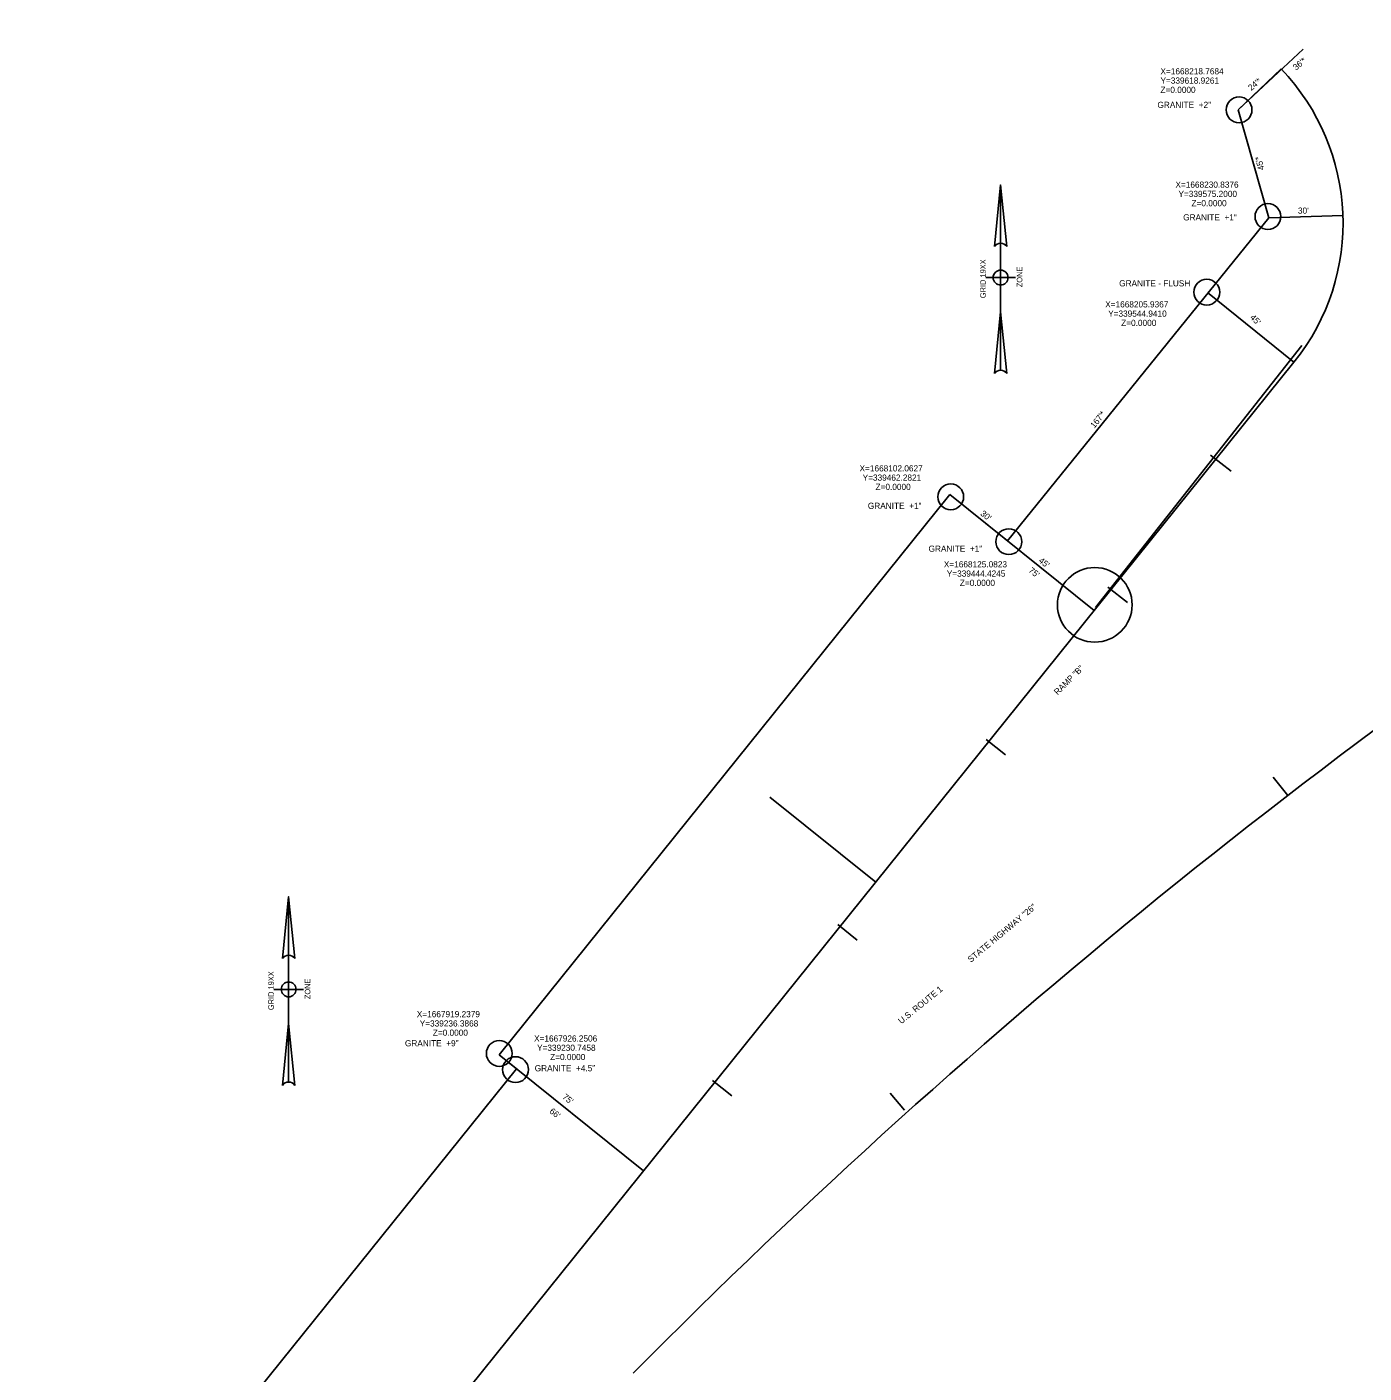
# Model space of a CAD drawing. Extents: x 1663896 to 1668965, y 337017 to 340013.
# Drawn here: x 1667728 to 1668269, y 339108 to 339653 of the extents above; entities that cross this region are included whole.
import ezdxf

# ---------------------------------------------------------------- set-up
doc = ezdxf.new("R2010")
doc.units = 0
for name, color, linetype in [('E_ROW_Line', 7, 'Continuous'), ('E_ROW_TieLine', 7, 'Continuous'), ('MISCELLN TEXT', 7, 'Continuous'), ('North Arrows', 7, 'Continuous')]:
    doc.layers.add(name, color=color, linetype=linetype)

msp = doc.modelspace()

# ---------------------------------------------------------------- linework, layer by layer
at = {"layer": 'E_ROW_Line'}
for p, q in [((1668218.45, 339618.89), (1668230.84, 339575.2)), ((1668230.84, 339575.2), (1668125.08, 339444.42)), ((1667919.24, 339236.39), (1668101.71, 339463.23)), ((1668125.08, 339444.42), (1668101.71, 339463.23)), ((1667926.25, 339230.75), (1667919.24, 339236.39)), ((1667728.11, 338984.42), (1667926.25, 339230.75))]:
    msp.add_line(p, q, dxfattribs=at)
at = {"layer": 'E_ROW_TieLine'}
for p, q in [((1668218.45, 339618.89), (1668244.77, 339643.45)), ((1668235.75, 339635.52), (1668218.45, 339618.89)), ((1668218.45, 339618.89), (1668230.84, 339575.2)), ((1668260.82, 339576.23), (1668230.84, 339575.2)), ((1668230.84, 339575.2), (1668125.08, 339444.42)), ((1668241, 339516.74), (1668205.94, 339544.94)), ((1668160.69, 339417.44), (1668244.23, 339523.48)), ((1667779.54, 338943.05), (1668241, 339516.74)), ((1668207.16, 339479.09), (1668215.59, 339472.67)), ((1667919.24, 339236.39), (1668101.71, 339463.23)), ((1668160.15, 339416.22), (1668101.71, 339463.23)), ((1668165.66, 339425.75), (1668173.56, 339419.45)), ((1668116.38, 339364.11), (1668124.27, 339357.8)), ((1668232.52, 339348.8), (1668238.48, 339341.4)), ((1668071.7, 339306.26), (1668028.84, 339340.73)), ((1668071.69, 339306.26), (1668071.69, 339306.26)), ((1668056.31, 339289.09), (1668064.13, 339282.78)), ((1667977.68, 339189.38), (1667919.24, 339236.39)), ((1667728.11, 338984.42), (1667926.25, 339230.75)), ((1668005.65, 339226.03), (1668013.46, 339219.78)), ((1668077.57, 339220.84), (1668083.39, 339213.98)), ((1667977.68, 339189.38), (1667977.68, 339189.38))]:
    msp.add_line(p, q, dxfattribs=at)
msp.add_circle((1668160.37, 339418.55), 15.11, dxfattribs=at)
for centre, radius, start, end in [((1669846.92, 337251.97), 2636.79, 109.53446, 135.27307), ((1668170.87, 339573.15), 90, 321.1872, 43.8705)]:
    msp.add_arc(centre, radius, start, end, dxfattribs=at)
at = {"layer": 'MISCELLN TEXT'}
for centre in [(1668218.77, 339618.93), (1668230.46, 339575.74), (1668205.7, 339545.14), (1668102.06, 339462.28), (1668125.56, 339444.13), (1667919.32, 339236.96), (1667925.88, 339230.4)]:
    msp.add_circle(centre, 5.23, dxfattribs=at)
at = {"layer": 'North Arrows'}
for p, q in [((1668119.74, 339563.56), (1668122.24, 339588.56)), ((1668122.24, 339588.56), (1668122.24, 339513.56)), ((1668122.24, 339588.56), (1668124.74, 339563.56)), ((1668116.24, 339551.06), (1668128.24, 339551.06)), ((1668119.74, 339512.22), (1668122.24, 339537.22)), ((1668122.24, 339537.22), (1668124.74, 339512.22)), ((1667831.55, 339275.37), (1667834.05, 339300.37)), ((1667834.05, 339300.37), (1667834.05, 339225.37)), ((1667834.05, 339300.37), (1667836.55, 339275.37)), ((1667828.05, 339262.87), (1667840.05, 339262.87)), ((1667831.55, 339224.03), (1667834.05, 339249.03)), ((1667834.05, 339249.03), (1667836.55, 339224.03))]:
    msp.add_line(p, q, dxfattribs=at)
for points in [[(1668122.24, 339564.91), (1668122.24, 339588.56), (1668119.74, 339563.56)], [(1668124.74, 339563.56), (1668122.24, 339588.56), (1668122.24, 339564.91)], [(1668122.24, 339554.06), (1668122.24, 339551.06), (1668125.24, 339551.06)], [(1668122.24, 339548.06), (1668122.24, 339551.06), (1668119.24, 339551.06)], [(1668122.24, 339513.56), (1668122.24, 339537.22), (1668119.74, 339512.22)], [(1668124.74, 339512.22), (1668122.24, 339537.22), (1668122.24, 339513.56)], [(1667834.05, 339276.71), (1667834.05, 339300.37), (1667831.55, 339275.37)], [(1667836.55, 339275.37), (1667834.05, 339300.37), (1667834.05, 339276.71)], [(1667834.05, 339265.87), (1667834.05, 339262.87), (1667837.05, 339262.87)], [(1667834.05, 339259.87), (1667834.05, 339262.87), (1667831.05, 339262.87)], [(1667834.05, 339225.37), (1667834.05, 339249.03), (1667831.55, 339224.03)], [(1667836.55, 339224.03), (1667834.05, 339249.03), (1667834.05, 339225.37)]]:
    msp.add_lwpolyline(points, dxfattribs=at)
for centre in [(1668122.24, 339551.06), (1667834.05, 339262.87)]:
    msp.add_circle(centre, 3, dxfattribs=at)
for centre, start, end in [((1668122.24, 339561.91), 33.5573, 146.4427), ((1668122.24, 339561.91), 90, 146.4427), ((1668122.24, 339561.91), 33.5573, 90), ((1668122.24, 339551.06), 0, 90), ((1668122.24, 339551.06), 180, 270), ((1668122.24, 339510.56), 33.5573, 146.4427), ((1668122.24, 339510.56), 90, 146.4427), ((1668122.24, 339510.56), 33.5573, 90), ((1667834.05, 339273.71), 33.5573, 146.4427), ((1667834.05, 339273.71), 90, 146.4427), ((1667834.05, 339273.71), 33.5573, 90), ((1667834.05, 339262.87), 0, 90), ((1667834.05, 339262.87), 180, 270), ((1667834.05, 339222.37), 33.5573, 146.4427), ((1667834.05, 339222.37), 90, 146.4427), ((1667834.05, 339222.37), 33.5573, 90)]:
    msp.add_arc(centre, 3, start, end, dxfattribs=at)

# ---------------------------------------------------------------- texts
at = {"layer": 'E_ROW_TieLine'}
for s, p in [('X=1668218.7684', (1668186.96, 339633.29)), ('Y=339618.9261', (1668186.96, 339629.54)), ('Z=0.0000', (1668186.96, 339625.79))]:
    msp.add_text(s, height=2.5, dxfattribs=at).set_placement(p)
at = {"layer": 'MISCELLN TEXT'}
for s, rotation, p in [("36'*", 40.547, (1668241.88, 339634.8)), ("24'*", 40.547, (1668223.71, 339626.52)), ("45'*", 105.8279, (1668229.08, 339594.89)), ("45'", 314.4624, (1668223, 339534.69)), ("167'*", 51.0383, (1668160.22, 339489.86)), ("30'", 321.1872, (1668113.82, 339455.09)), ("75'", 321.3385, (1668133.35, 339432.08)), ("45'", 321.3385, (1668137.39, 339436.02)), ('RAMP "B"', 44.6441, (1668145.32, 339381.88)), ('STATE HIGHWAY "26"', 39.7828, (1668110.21, 339273.63)), ('U.S. ROUTE 1', 39.0939, (1668082.05, 339248.71)), ("75'", 321.3385, (1667944.64, 339218.92)), ("66'", 321.3385, (1667939.39, 339213.15))]:
    msp.add_text(s, height=2.5, rotation=rotation, dxfattribs=at).set_placement(p)
for s, p in [('GRANITE  +2"', (1668185.73, 339619.7)), ('X=1668230.8376', (1668193.02, 339587.41)), ('Y=339575.2000', (1668194.24, 339583.66)), ('Z=0.0000', (1668199.52, 339579.91)), ('GRANITE  +1"', (1668196.14, 339574.17)), ("30'", (1668242.62, 339576.89)), ('GRANITE - FLUSH', (1668170.24, 339547.47)), ('X=1668205.9367', (1668164.59, 339538.95)), ('Y=339544.9410', (1668165.78, 339535.2)), ('Z=0.0000', (1668171.06, 339531.45)), ('X=1668102.0627', (1668065.15, 339472.56)), ('Y=339462.2821', (1668066.4, 339468.81)), ('Z=0.0000', (1668071.63, 339465.06)), ('GRANITE  +1"', (1668068.51, 339457.39)), ('GRANITE  +1"', (1668093.08, 339440.04)), ('X=1668125.0823', (1668099.27, 339433.71)), ('Y=339444.4245', (1668100.47, 339429.96)), ('Z=0.0000', (1668105.75, 339426.21)), ('X=1667919.2379', (1667885.93, 339251.61)), ('Y=339236.3868', (1667887.1, 339247.86)), ('Z=0.0000', (1667892.4, 339244.11)), ('X=1667926.2506', (1667933.4, 339241.76)), ('GRANITE  +9"', (1667881.12, 339239.83)), ('Y=339230.7458', (1667934.6, 339238.01)), ('GRANITE  +4.5"', (1667933.65, 339229.72)), ('Z=0.0000', (1667939.9, 339234.26))]:
    msp.add_text(s, height=2.5, dxfattribs=at).set_placement(p)
at = {"layer": 'North Arrows'}
for s, p in [('GRID 19XX', (1668116.24, 339542.69)), ('ZONE', (1668131.05, 339547.12)), ('GRID 19XX', (1667828.05, 339254.5)), ('ZONE', (1667842.85, 339258.93))]:
    msp.add_text(s, height=2.249, rotation=90, dxfattribs=at).set_placement(p)

doc.saveas('drawing.dxf')
